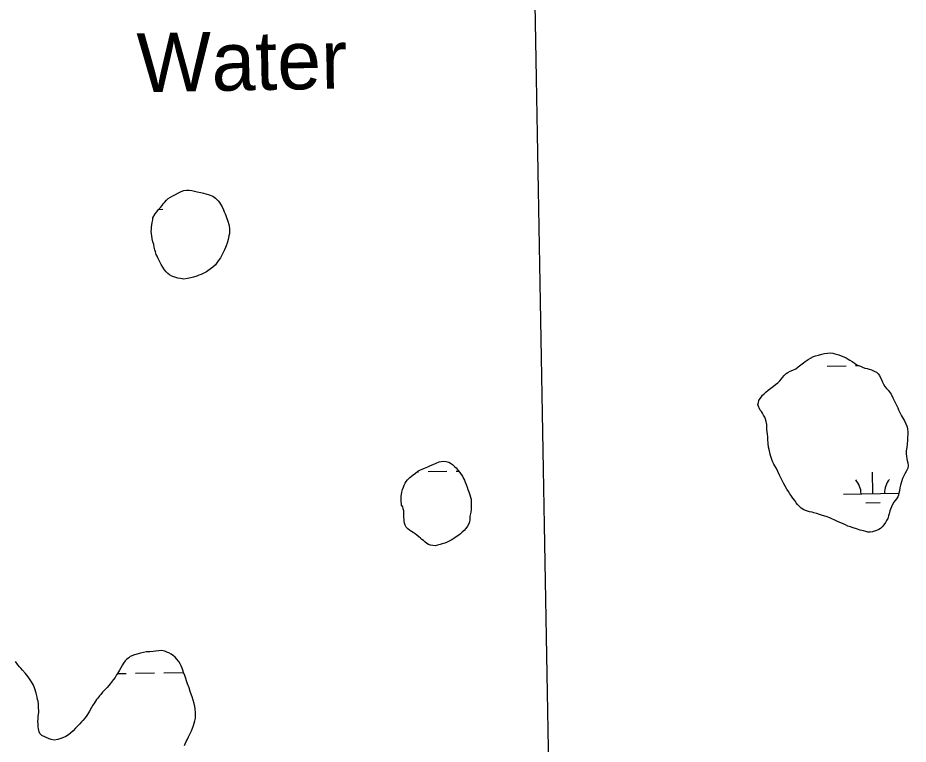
# Model space of a CAD drawing. Extents: x 3925854 to 3964121, y 224593 to 250589.
# Drawn here: x 3934483 to 3935992, y 233066 to 234297 of the extents above; entities that cross this region are included whole.
import ezdxf

# ---------------------------------------------------------------- set-up
doc = ezdxf.new("R2010")
doc.units = 0
for name, color, linetype in [('V-GRID-MAJR', 7, 'Continuous'), ('V-RIVR-IDEN', 7, 'Continuous'), ('V-WETL-SWMP', 7, 'Continuous')]:
    doc.layers.add(name, color=color, linetype=linetype)

msp = doc.modelspace()

# ---------------------------------------------------------------- linework, layer by layer
at = {"layer": 'V-GRID-MAJR'}
msp.add_spline([(3935435.519, 230124.471), (3935327.129, 236182.494), (3935218.705, 242242.439), (3935110.281, 248302.374), (3935110.246, 248304.307)], degree=3, dxfattribs=at)
at = {"layer": 'V-WETL-SWMP'}
for p, q in [((3934721.93, 233972.51), (3934729.308, 233972.644)), ((3935855.207, 233706.824), (3935887.202, 233707.406)), ((3935903.199, 233707.697), (3935908.399, 233707.791)), ((3935160.045, 233527.655), (3935162.533, 233527.7)), ((3935178.53, 233527.991), (3935210.525, 233528.573)), ((3935226.522, 233528.864), (3935230.663, 233528.939)), ((3935932.552, 233490.951), (3935931.898, 233526.945)), ((3935882.561, 233490.042), (3935976.864, 233491.757)), ((3935920.835, 233475.305), (3935944.831, 233475.741)), ((3934673.895, 233214.517), (3934671.276, 233212.628)), ((3934680.848, 233217.537), (3934673.895, 233214.517)), ((3934687.191, 233219.464), (3934680.848, 233217.537)), ((3934691.216, 233220.436), (3934687.191, 233219.464)), ((3934696.174, 233221.263), (3934691.216, 233220.436)), ((3934701.594, 233222.405), (3934696.174, 233221.263)), ((3934707.022, 233222.771), (3934701.594, 233222.405)), ((3934712.914, 233223.297), (3934707.022, 233222.771)), ((3934716.789, 233223.802), (3934712.914, 233223.297)), ((3934722.371, 233224.325), (3934716.789, 233223.802)), ((3934726.868, 233224.681), (3934722.371, 233224.325)), ((3934732.467, 233223.497), (3934726.868, 233224.681)), ((3934735.585, 233222.132), (3934732.467, 233223.497)), ((3934739.013, 233220.77), (3934735.585, 233222.132)), ((3934743.382, 233218.487), (3934739.013, 233220.77)), ((3934746.978, 233215.886), (3934743.382, 233218.487)), ((3934749.95, 233213.588), (3934746.978, 233215.886)), ((3934483.301, 233200.772), (3934479.212, 233206.006)), ((3934486.129, 233197.386), (3934483.301, 233200.772)), ((3934660.537, 233200.413), (3934657.947, 233195.73)), ((3934662.214, 233203.379), (3934660.537, 233200.413)), ((3934665.12, 233207.599), (3934662.214, 233203.379)), ((3934667.27, 233209.793), (3934665.12, 233207.599)), ((3934671.276, 233212.628), (3934667.27, 233209.793)), ((3934752.462, 233210.82), (3934749.95, 233213.588)), ((3934756.077, 233206.357), (3934752.462, 233210.82)), ((3934758.604, 233202.037), (3934756.077, 233206.357)), ((3934760.189, 233198.794), (3934758.604, 233202.037)), ((3934488.172, 233194.924), (3934486.129, 233197.386)), ((3934491, 233191.539), (3934488.172, 233194.924)), ((3934496.026, 233185.693), (3934491, 233191.539)), ((3934500.58, 233180.463), (3934496.026, 233185.693)), ((3934651.993, 233186.047), (3934650.469, 233183.393)), ((3934651.784, 233185.683), (3934666.756, 233185.956)), ((3934655.353, 233191.358), (3934651.993, 233186.047)), ((3934657.947, 233195.73), (3934655.353, 233191.358)), ((3934682.753, 233186.247), (3934714.748, 233186.828)), ((3934730.745, 233187.119), (3934762.74, 233187.701)), ((3934761.624, 233195.084), (3934760.189, 233198.794)), ((3934762.745, 233191.681), (3934761.624, 233195.084)), ((3934764.341, 233187.352), (3934762.745, 233191.681)), ((3934766.253, 233182.561), (3934764.341, 233187.352)), ((3934502.944, 233176.917), (3934500.58, 233180.463)), ((3934506.254, 233171.985), (3934502.944, 233176.917)), ((3934509.573, 233166.122), (3934506.254, 233171.985)), ((3934645.118, 233175.424), (3934639.759, 233168.385)), ((3934648.182, 233179.335), (3934645.118, 233175.424)), ((3934650.469, 233183.393), (3934648.182, 233179.335)), ((3934768.014, 233177.302), (3934766.253, 233182.561)), ((3934769.138, 233173.589), (3934768.014, 233177.302)), ((3934770.899, 233168.33), (3934769.138, 233173.589)), ((3934512.123, 233159.629), (3934509.573, 233166.122)), ((3934514.058, 233152.51), (3934512.123, 233159.629)), ((3934627.025, 233153.977), (3934623.958, 233150.376)), ((3934629.173, 233156.327), (3934627.025, 233153.977)), ((3934632.554, 233159.62), (3934629.173, 233156.327)), ((3934634.703, 233161.97), (3934632.554, 233159.62)), ((3934637.768, 233165.726), (3934634.703, 233161.97)), ((3934639.759, 233168.385), (3934637.768, 233165.726)), ((3934773.452, 233161.528), (3934770.899, 233168.33)), ((3934775.534, 233155.186), (3934773.452, 233161.528)), ((3934777.457, 233149.308), (3934775.534, 233155.186)), ((3934515.987, 233146.012), (3934514.058, 233152.51)), ((3934516.807, 233141.675), (3934515.987, 233146.012)), ((3934517.613, 233138.734), (3934516.807, 233141.675)), ((3934616.753, 233141.611), (3934613.238, 233136.299)), ((3934618.745, 233144.115), (3934616.753, 233141.611)), ((3934621.654, 233148.024), (3934618.745, 233144.115)), ((3934623.958, 233150.376), (3934621.654, 233148.024)), ((3934778.731, 233146.062), (3934777.457, 233149.308)), ((3934780.494, 233140.649), (3934778.731, 233146.062)), ((3934782.104, 233134.923), (3934780.494, 233140.649)), ((3934518.283, 233133.93), (3934517.613, 233138.734)), ((3934518.481, 233129.742), (3934518.283, 233133.93)), ((3934518.578, 233120.276), (3934518.481, 233129.742)), ((3934607.891, 233128.019), (3934604.694, 233121.933)), ((3934610.488, 233132.08), (3934607.891, 233128.019)), ((3934613.238, 233136.299), (3934610.488, 233132.08)), ((3934783.085, 233130.122), (3934782.104, 233134.923)), ((3934783.745, 233126.249), (3934783.085, 233130.122)), ((3934784.437, 233119.272), (3934783.745, 233126.249)), ((3934517.185, 233104.742), (3934517.456, 233108.625)), ((3934517.456, 233108.625), (3934517.875, 233113.13)), ((3934517.875, 233113.13), (3934518.578, 233120.276)), ((3934597.205, 233110.683), (3934593.371, 233106.143)), ((3934600.421, 233114.906), (3934597.205, 233110.683)), ((3934602.861, 233119.121), (3934600.421, 233114.906)), ((3934604.694, 233121.933), (3934602.861, 233119.121)), ((3934783.177, 233105.912), (3934784.218, 233110.424)), ((3934784.218, 233110.424), (3934784.651, 233113.532)), ((3934784.651, 233113.532), (3934784.437, 233119.272)), ((3934517.54, 233100.4), (3934517.185, 233104.742)), ((3934517.747, 233095.281), (3934517.54, 233100.4)), ((3934518.093, 233091.87), (3934517.747, 233095.281)), ((3934585.084, 233097.057), (3934581.09, 233092.981)), ((3934588.461, 233100.661), (3934585.084, 233097.057)), ((3934591.223, 233103.793), (3934588.461, 233100.661)), ((3934593.371, 233106.143), (3934591.223, 233103.793)), ((3934779.428, 233093.148), (3934781.087, 233097.821)), ((3934781.087, 233097.821), (3934782.134, 233101.711)), ((3934782.134, 233101.711), (3934783.177, 233105.912)), ((3934519.382, 233087.228), (3934518.093, 233091.87)), ((3934520.812, 233083.983), (3934519.382, 233087.228)), ((3934523.945, 233081.067), (3934520.812, 233083.983)), ((3934529.875, 233077.868), (3934523.945, 233081.067)), ((3934564.471, 233079.153), (3934557.984, 233076.138)), ((3934569.253, 233081.996), (3934564.471, 233079.153)), ((3934572.485, 233084.667), (3934569.253, 233081.996)), ((3934576.942, 233088.903), (3934572.485, 233084.667)), ((3934581.09, 233092.981), (3934576.942, 233088.903)), ((3934770.009, 233073.342), (3934772.591, 233078.8)), ((3934772.591, 233078.8), (3934777.455, 233088.782)), ((3934777.455, 233088.782), (3934779.428, 233093.148)), ((3934536.422, 233075.142), (3934529.875, 233077.868)), ((3934540.003, 233073.937), (3934536.422, 233075.142)), ((3934544.979, 233073.056), (3934540.003, 233073.937)), ((3934550.864, 233074.203), (3934544.979, 233073.056)), ((3934557.984, 233076.138), (3934550.864, 233074.203)), ((3934765.759, 233063.987), (3934766.97, 233066.948)), ((3934766.97, 233066.948), (3934768.642, 233070.379)), ((3934768.642, 233070.379), (3934770.009, 233073.342))]:
    msp.add_line(p, q, dxfattribs=at)
for points in [[(3934711.831, 233954.891), (3934712.292, 233958.018), (3934716.001, 233964.959), (3934718.595, 233968.436), (3934721.841, 233972.414), (3934724.93, 233975.732), (3934727.688, 233979.212), (3934729.635, 233981.697), (3934731.744, 233984.348), (3934735.322, 233988), (3934738.252, 233990.824), (3934742.006, 233993.328), (3934745.765, 233995.338), (3934750.345, 233997.522), (3934755.573, 234000.533), (3934760.315, 234002.883), (3934764.903, 234004.244), (3934769.331, 234005.112), (3934773.438, 234005.318), (3934778.049, 234004.379), (3934782.494, 234003.603), (3934787.272, 234002.501), (3934793.368, 234000.92), (3934798.144, 233999.983), (3934801.934, 233999.036), (3934807.705, 233997.123), (3934813.646, 233994.718), (3934818.281, 233991.479), (3934822.762, 233987.252), (3934825.094, 233984.153), (3934826.765, 233981.541), (3934829.609, 233976.639), (3934831.633, 233971.565), (3934832.983, 233968.128), (3934834.492, 233965.185), (3934835.671, 233962.403), (3934837.026, 233958.473), (3934839.39, 233952.252), (3934841.091, 233946.682), (3934842.137, 233940.776), (3934842.033, 233934.858), (3934841.903, 233931.57), (3934840.957, 233927.616), (3934839.703, 233921.687), (3934837.961, 233915.26), (3934836.197, 233910.969), (3934835.077, 233907.999), (3934833.476, 233903.874), (3934830.741, 233898.094), (3934828.799, 233895.116), (3934826.544, 233890.655), (3934824.442, 233887.347), (3934821.853, 233883.376), (3934818.122, 233878.572), (3934813.563, 233874.417), (3934809.49, 233870.924), (3934805.575, 233868.09), (3934802.96, 233866.584), (3934798.381, 233864.401), (3934794.129, 233862.385), (3934789.871, 233860.862), (3934786.598, 233859.514), (3934781.028, 233857.814), (3934776.276, 233856.45), (3934771.027, 233855.41), (3934764.793, 233854.361), (3934759.032, 233855.288), (3934754.258, 233856.061), (3934750.795, 233857.176), (3934747.659, 233858.458), (3934744.361, 233859.575), (3934740.068, 233861.503), (3934737.415, 233863.777), (3934734.426, 233866.869), (3934731.763, 233870.128), (3934728.925, 233874.372), (3934726.081, 233879.274), (3934723.395, 233884.834), (3934720.546, 233890.228), (3934719.203, 233893.008), (3934717.858, 233895.953), (3934716.498, 233900.376), (3934715.639, 233903.983), (3934714.443, 233908.408), (3934713.576, 233912.836), (3934712.049, 233917.587), (3934711.178, 233922.344), (3934710.63, 233927.762), (3934710.103, 233931.043), (3934709.407, 233934.816), (3934709.695, 233938.763), (3934709.824, 233942.216), (3934710.438, 233946.495), (3934710.73, 233950.114)], [(3935135.665, 233468.171), (3935133.625, 233471.391), (3935132.926, 233479.408), (3935133.198, 233482.96), (3935133.165, 233486.201), (3935133.749, 233489.447), (3935134.327, 233493.311), (3935135.517, 233497.644), (3935136.712, 233501.514), (3935137.912, 233504.922), (3935139.727, 233508.489), (3935141.55, 233511.286), (3935143.988, 233514.397), (3935147.499, 233518.137), (3935150.407, 233520.481), (3935153.316, 233522.671), (3935157.144, 233525.643), (3935161.434, 233528.619), (3935165.884, 233531.133), (3935168.649, 233532.396), (3935172.799, 233533.982), (3935178.021, 233536.35), (3935182.632, 233538.249), (3935187.087, 233540.146), (3935192.31, 233542.514), (3935197.537, 233544.42), (3935201.077, 233545.382), (3935205.238, 233545.887), (3935209.566, 233545.16), (3935213.745, 233543.968), (3935216.694, 233542.301), (3935219.801, 233540.327), (3935223.693, 233536.972), (3935226.345, 233534.221), (3935229.782, 233530.09), (3935232.597, 233526.415), (3935234.947, 233523.044), (3935236.982, 233520.133), (3935238.716, 233516.601), (3935240.292, 233513.377), (3935241.406, 233510.147), (3935243.142, 233506.307), (3935244.887, 233501.695), (3935246.318, 233497.543), (3935247.748, 233493.546), (3935249.184, 233488.931), (3935250.619, 233484.47), (3935251.575, 233481.548), (3935251.918, 233478.157), (3935251.964, 233473.682), (3935251.865, 233468.28), (3935251.758, 233463.649), (3935251.186, 233459.168), (3935250.152, 233454.682), (3935249.566, 233451.59), (3935249.156, 233446.493), (3935248.727, 233443.094), (3935247.528, 233439.687), (3935245.254, 233435.651), (3935242.671, 233431.767), (3935239.775, 233428.188), (3935236.719, 233425.225), (3935233.657, 233422.879), (3935230.749, 233420.534), (3935226.458, 233417.558), (3935224.008, 233415.681), (3935220.483, 233413.33), (3935217.569, 233411.603), (3935214.188, 233410.18), (3935210.81, 233408.602), (3935206.814, 233407.018), (3935202.814, 233405.742), (3935199.122, 233404.624), (3935194.658, 233403.498), (3935190.656, 233402.531), (3935186.643, 233402.645), (3935182.621, 233403.529), (3935179.368, 233404.731), (3935176.729, 233406.247), (3935173.154, 233408.834), (3935170.814, 233411.279), (3935168.325, 233413.26), (3935165.834, 233415.394), (3935163.187, 233417.682), (3935159.765, 233420.271), (3935156.657, 233422.399), (3935153.239, 233424.679), (3935150.597, 233426.504), (3935147.333, 233428.785), (3935144.533, 233430.917), (3935141.568, 233434.127), (3935139.836, 233437.504), (3935138.725, 233440.579), (3935138.076, 233443.659), (3935137.89, 233446.744), (3935137.699, 233450.291), (3935137.663, 233453.84), (3935137.466, 233458.004), (3935137.275, 233461.552), (3935136.625, 233464.786)]]:
    msp.add_lwpolyline(points, close=True, dxfattribs=at)
for points in [[(3935741.843, 233632.241), (3935737.892, 233641.305), (3935738.468, 233645.324), (3935739.517, 233648.421), (3935741.486, 233651.99), (3935743.771, 233654.946), (3935745.751, 233657.435), (3935748.196, 233659.775), (3935751.254, 233662.584), (3935755.078, 233665.864), (3935759.826, 233669.461), (3935764.266, 233672.902), (3935767.632, 233675.714), (3935771.768, 233678.688), (3935774.824, 233681.652), (3935777.567, 233685.075), (3935779.237, 233687.715), (3935781.981, 233690.984), (3935785.499, 233694.106), (3935788.257, 233695.986), (3935792.554, 233698.345), (3935797.01, 233700.242), (3935801.925, 233702.453), (3935806.214, 233705.583), (3935810.5, 233709.022), (3935814.94, 233712.463), (3935817.851, 233714.499), (3935822.752, 233718.098), (3935826.895, 233720.455), (3935832.116, 233722.978), (3935835.345, 233724.091), (3935840.73, 233725.689), (3935846.116, 233727.133), (3935850.888, 233728.262), (3935855.974, 233728.932), (3935860.756, 233729.135), (3935864.618, 233728.712), (3935868.022, 233727.82), (3935874.676, 233726.037), (3935879.012, 233724.538), (3935883.353, 233722.576), (3935887.075, 233720.762), (3935890.647, 233718.639), (3935893.75, 233716.973), (3935897.631, 233714.698), (3935900.895, 233712.416), (3935903.539, 233710.437), (3935906.8, 233708.465), (3935911.449, 233706.506), (3935914.858, 233705.152), (3935918.886, 233703.65), (3935922.754, 233702.61), (3935926.16, 233701.564), (3935930.493, 233700.374), (3935934.678, 233698.565), (3935938.712, 233696.446), (3935941.825, 233693.854), (3935943.707, 233690.941), (3935945.125, 233688.024), (3935947.016, 233684.185), (3935948.914, 233679.73), (3935950.649, 233676.044), (3935952.846, 233672.517), (3935955.661, 233668.842), (3935958.468, 233665.939), (3935960.498, 233663.645), (3935963.477, 233659.046), (3935966.469, 233653.212), (3935969.459, 233647.533), (3935972.298, 233641.544), (3935974.824, 233636.014), (3935976.245, 233632.788), (3935978.453, 233628.181), (3935981.289, 233622.5), (3935984.276, 233617.13), (3935986.005, 233614.061), (3935988.524, 233609.149), (3935990.585, 233603.769), (3935991.239, 233600.226), (3935991.907, 233595.295), (3935991.952, 233590.82), (3935991.532, 233586.649), (3935991.279, 233581.246), (3935990.729, 233574.604), (3935990.018, 233568.733), (3935989.303, 233563.17), (3935989.048, 233557.921), (3935989.395, 233554.221), (3935990.211, 233549.908), (3935991.015, 233546.676), (3935991.979, 233542.982), (3935992.491, 233538.203), (3935991.765, 233533.721), (3935989.802, 233529.534), (3935986.768, 233524.41), (3935984.951, 233520.997), (3935982.684, 233516.344), (3935980.891, 233510.616), (3935979.556, 233505.356), (3935978.524, 233500.561), (3935977.649, 233495.614)], [(3935977.649, 233495.614), (3935976.768, 233491.284), (3935976.031, 233487.882), (3935974.671, 233485.09), (3935972.695, 233482.138), (3935970.41, 233479.182), (3935967.973, 233476.071), (3935965.852, 233472.191), (3935964.042, 233468.161), (3935962.535, 233464.596), (3935961.641, 233461.5), (3935960.455, 233456.704), (3935959.26, 233452.834), (3935957.76, 233448.652), (3935955.946, 233444.93), (3935954.128, 233441.671), (3935951.39, 233437.785), (3935948.184, 233434.357), (3935945.278, 233431.858), (3935942.675, 233429.826), (3935938.525, 233428.24), (3935935.604, 233427.13), (3935931.91, 233426.166), (3935927.754, 233425.198), (3935924.354, 233425.626), (3935920.642, 233426.514), (3935916.619, 233427.553), (3935911.357, 233429.042), (3935905.01, 233430.983), (3935899.127, 233432.775), (3935894.482, 233434.271), (3935890.455, 233435.772), (3935886.424, 233437.583), (3935882.546, 233439.549), (3935878.054, 233441.201), (3935873.559, 233443.161), (3935867.979, 233445.573), (3935863.171, 233447.839), (3935859.449, 233449.652), (3935853.409, 233451.751), (3935847.37, 233453.85), (3935842.416, 233455.342), (3935837.617, 233456.836), (3935832.665, 233458.174), (3935829.57, 233459.069), (3935825.392, 233460.106), (3935820.285, 233461.597), (3935815.638, 233463.247), (3935811.291, 233465.826), (3935808.172, 233469.035), (3935804.897, 233472.396), (3935802.864, 233474.999), (3935800.201, 233478.829), (3935797.07, 233483.273), (3935793.78, 233488.023), (3935791.902, 233490.627), (3935789.548, 233494.461), (3935786.884, 233498.446), (3935784.057, 233503.201), (3935781.225, 233508.573), (3935778.712, 233512.868), (3935777.132, 233516.401), (3935774.605, 233522.085), (3935771.612, 233528.073), (3935769.091, 233533.139), (3935766.264, 233537.894), (3935764.695, 233540.502), (3935762.961, 233544.033), (3935761.374, 233548.338), (3935759.465, 233553.874), (3935758.5, 233557.722), (3935757.207, 233563.418), (3935755.755, 233569.576), (3935754.922, 233575.586), (3935754.39, 233582.371), (3935754.346, 233586.691), (3935754.136, 233592.09), (3935753.641, 233595.171), (3935753.131, 233599.796), (3935753.089, 233603.962), (3935753.047, 233607.974), (3935751.914, 233613.209), (3935750.793, 233617.21), (3935749.527, 233620.283), (3935747.487, 233623.503), (3935745.755, 233626.88), (3935744.025, 233630.103), (3935741.843, 233632.241)]]:
    msp.add_lwpolyline(points, dxfattribs=at)
for centre, start, end in [((3935877.31, 233490.422), 0.269879, 41.813537), ((3935987.777, 233492.43), 140.269876, 181.813534)]:
    msp.add_arc(centre, 35.246, start, end, dxfattribs=at)

# ---------------------------------------------------------------- texts
at = {"layer": 'V-RIVR-IDEN'}
msp.add_text('Water', height=99.9998, rotation=1.078661, dxfattribs=at).set_placement((3934686.005, 234170.823))

doc.saveas('drawing.dxf')
